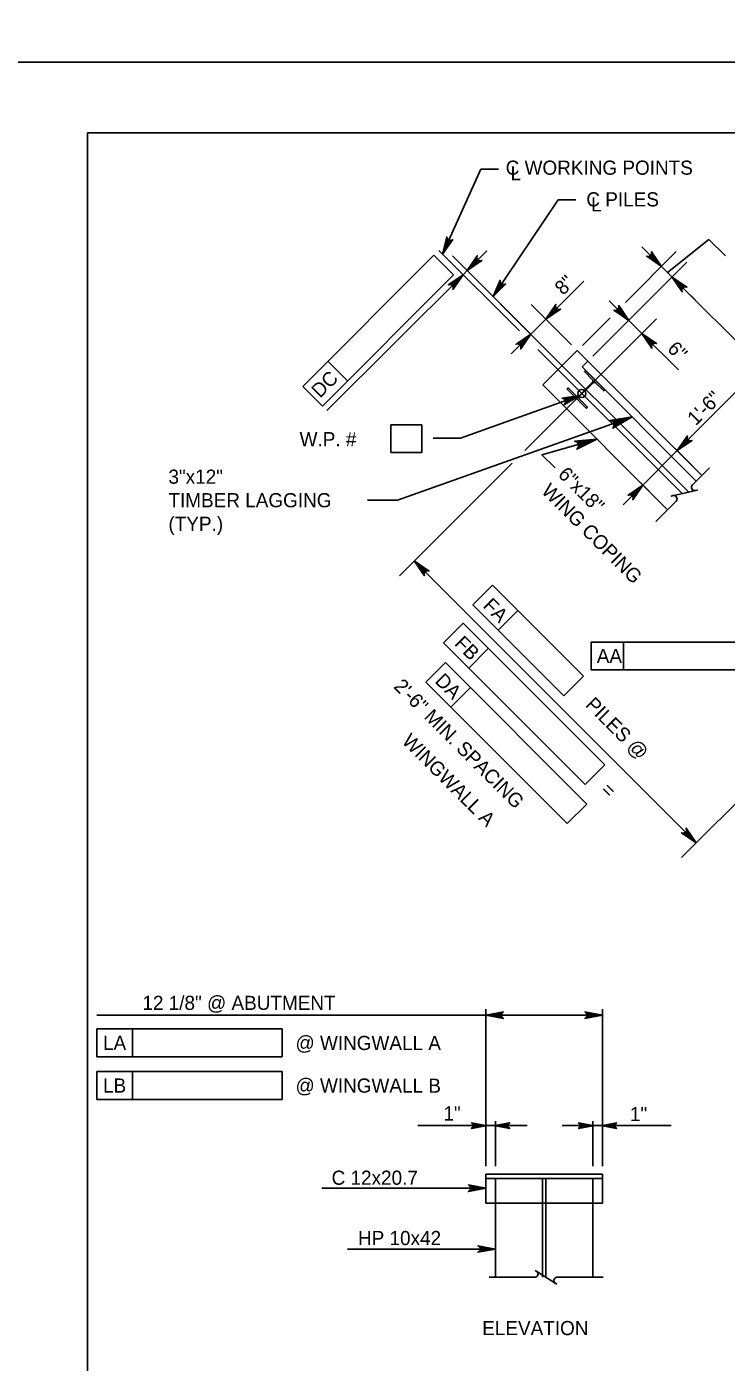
# Model space of a CAD drawing. Extents: x 638304 to 640306, y 296653 to 298435.
# Drawn here: x 639303.6 to 639451.8, y 297565.8 to 297849 of the extents above; entities that cross this region are included whole.
import ezdxf

# ---------------------------------------------------------------- set-up
doc = ezdxf.new("R2010")
doc.units = 0
for name, color, linetype in [('1', 7, 'Continuous'), ('2', 7, 'Continuous'), ('3', 7, 'Continuous'), ('4', 7, 'Continuous'), ('Level 2', 7, 'Continuous'), ('Level 3', 7, 'Continuous'), ('Level 4', 7, 'Continuous'), ('Level 5', 7, 'Continuous'), ('Level 52', 7, 'Continuous'), ('Level 8', 7, 'Continuous'), ('PLT-BNDY', 7, 'Continuous')]:
    doc.layers.add(name, color=color, linetype=linetype)

# ---------------------------------------------------------------- blocks, each defined once
blk = doc.blocks.new('HPILE')
at = {"layer": '3'}
for p, q in [((-0.12, -2.66), (-0.12, 2.66)), ((0.12, 2.66), (0.12, -2.66)), ((-3.67, -3.1), (-0.56, -3.1))]:
    blk.add_line(p, q, dxfattribs=at)
for points in [[(-0.56, 3.1), (-3.67, 3.1), (-3.67, 3.54), (3.67, 3.54), (3.67, 3.1), (0.56, 3.1)], [(0.56, -3.1), (3.67, -3.1), (3.67, -3.54), (-3.67, -3.54), (-3.67, -3.1)]]:
    blk.add_lwpolyline(points, dxfattribs=at)
for centre, start, end in [((-0.56, 2.66), 0, 90), ((0.56, 2.66), 90, 180), ((-0.56, -2.66), 270, 0), ((0.56, -2.66), 180, 270)]:
    blk.add_arc(centre, 0.438, start, end, dxfattribs=at)
blk = doc.blocks.new('LT')
at = {"layer": '1'}
blk.add_lwpolyline([(0, 0), (-11.2, -2.1), (-10.8, -1.8), (-10.3, -1.5), (-10.1, -1.1), (-9.9, -0.8), (-9.8, -0.4), (-9.8, 0), (-9.8, 0.4), (-9.9, 0.8), (-10.1, 1.1), (-10.3, 1.5), (-10.8, 1.8), (-11.2, 2.1), (0, 0), (-10.8, 1.8), (-10.3, 1.5), (0, 0), (-10.1, 1.1), (-9.9, 0.8), (0, 0), (-9.8, 0.4), (-9.8, 0), (0, 0), (-9.8, -0.4), (-9.9, -0.8), (0, 0), (-10.1, -1.1), (-10.3, -1.5), (0, 0), (-10.8, -1.8)], dxfattribs=at)

msp = doc.modelspace()

# ---------------------------------------------------------------- linework, layer by layer
at = {"layer": '2'}
for p, q in [((639316.46, 297262.46), (639316.46, 297826.46)), ((639316.46, 297826.46), (640102.46, 297826.46))]:
    msp.add_line(p, q, dxfattribs=at)
at = {"layer": '4'}
for p, q in [((639409.63, 297615.95), (639386.5, 297615.95)), ((639440.19, 297615.95), (639417.06, 297615.95))]:
    msp.add_line(p, q, dxfattribs=at)
at = {"layer": 'Level 2'}
for p, q in [((639420.25, 297780.28), (639412.95, 297772.99)), ((639446.69, 297753.83), (639420.25, 297780.28)), ((639439.4, 297746.54), (639412.95, 297772.99))]:
    msp.add_line(p, q, dxfattribs=at)
at = {"layer": 'Level 3'}
for p, q in [((639422.51, 297778.02), (639421.29, 297776.81)), ((639445.48, 297752.62), (639421.29, 297776.81)), ((639400.89, 297605.62), (639400.89, 297599.48)), ((639400.89, 297605.62), (639425.58, 297605.62)), ((639400.89, 297604.76), (639425.58, 297604.76)), ((639402.94, 297604.76), (639402.94, 297599.48)), ((639412.89, 297604.76), (639412.89, 297583.79)), ((639413.58, 297604.76), (639413.58, 297583.79)), ((639423.54, 297604.76), (639423.54, 297599.48)), ((639425.58, 297599.48), (639425.58, 297605.62)), ((639400.89, 297599.48), (639425.58, 297599.48)), ((639402.94, 297599.48), (639402.94, 297583.79)), ((639423.54, 297583.79), (639423.54, 297599.48)), ((639411.32, 297585.24), (639415.93, 297582.34)), ((639401.61, 297583.79), (639411.26, 297583.79)), ((639415.92, 297583.79), (639425.78, 297583.79))]:
    msp.add_line(p, q, dxfattribs=at)
for centre, start, end in [((639411.26, 297584.47), 270, 60), ((639415.98, 297583.12), 95.3286, 237.8672)]:
    msp.add_arc(centre, 0.681, start, end, dxfattribs=at)
at = {"layer": 'Level 4'}
for p, q in [((639399.8, 297818.72), (639403.57, 297818.72)), ((639416.22, 297812.24), (639419.97, 297812.24)), ((639439.41, 297796.82), (639448.16, 297803.87)), ((639448.16, 297803.87), (639451.65, 297800.38)), ((639362.06, 297772.69), (639389.85, 297800.48)), ((639389.85, 297800.48), (639394.02, 297796.31)), ((639407.98, 297784.45), (639390.9, 297801.52)), ((639410.2, 297783.97), (639393.79, 297800.38)), ((639396.92, 297797.25), (639401.08, 297801.42)), ((639430.45, 297790.49), (639441.22, 297801.26)), ((639440.35, 297795.87), (639433.93, 297802.3)), ((639438.1, 297798.13), (639435.49, 297800.73)), ((639396.91, 297797.25), (639396.05, 297796.38)), ((639423.59, 297779.11), (639443.48, 297799)), ((639366.23, 297768.52), (639394.02, 297796.31)), ((639396.05, 297796.38), (639367.21, 297767.55)), ((639413.58, 297786.95), (639421.64, 297795)), ((639499.58, 297736.64), (639440.35, 297795.87)), ((639443.13, 297793.09), (639445.22, 297791.01)), ((639443.88, 297750.29), (639403.95, 297790.21)), ((639419.05, 297781.48), (639410.46, 297790.07)), ((639423.59, 297779.11), (639434.29, 297789.81)), ((639431.17, 297786.69), (639427, 297790.85)), ((639437.07, 297787.03), (639409.13, 297759.09)), ((639410.4, 297783.76), (639413.58, 297786.95)), ((639421.33, 297781.37), (639427.23, 297787.26)), ((639431.17, 297786.69), (639433.95, 297783.91)), ((639410.4, 297783.76), (639406.23, 297779.6)), ((639433.95, 297783.91), (639441.68, 297776.18)), ((639442.46, 297749.97), (639411.91, 297780.51)), ((639367.4, 297778.03), (639371.57, 297773.86)), ((639441.46, 297759.07), (639457.07, 297774.69)), ((639362.06, 297772.69), (639366.23, 297768.52)), ((639380.76, 297764.56), (639387.33, 297764.56)), ((639380.76, 297758.66), (639380.76, 297764.56)), ((639387.33, 297758.66), (639387.33, 297764.56)), ((639387.33, 297758.66), (639380.76, 297758.66)), ((639434.16, 297751.78), (639441.46, 297759.07)), ((639441.02, 297759.51), (639444.58, 297755.95)), ((639406.46, 297756.42), (639382.59, 297732.55)), ((639434.16, 297751.78), (639429.99, 297747.61)), ((639433.72, 297752.22), (639437.29, 297748.65)), ((639445.48, 297675.91), (639385.71, 297735.67)), ((639402.29, 297730.52), (639398.13, 297726.35)), ((639402.29, 297730.52), (639421.55, 297711.26)), ((639398.13, 297726.35), (639417.39, 297707.09)), ((639407.63, 297725.18), (639403.46, 297721.02)), ((639396.07, 297722.47), (639391.9, 297718.31)), ((639396.07, 297722.47), (639426.08, 297692.46)), ((639391.9, 297718.31), (639421.91, 297688.3)), ((639423.21, 297718.45), (639458.44, 297718.45)), ((639423.21, 297712.56), (639423.21, 297718.45)), ((639430.04, 297712.56), (639430.04, 297718.45)), ((639401.4, 297717.14), (639397.24, 297712.97)), ((639392.3, 297714.15), (639388.13, 297709.98)), ((639392.3, 297714.15), (639422.31, 297684.14)), ((639458.44, 297712.56), (639423.21, 297712.56)), ((639388.13, 297709.98), (639418.14, 297679.98)), ((639421.55, 297711.26), (639417.39, 297707.09)), ((639479.91, 297710.34), (639442.35, 297672.78)), ((639397.64, 297708.82), (639393.47, 297704.65)), ((639426.08, 297692.46), (639421.91, 297688.3)), ((639422.31, 297684.14), (639418.14, 297679.98)), ((639400.89, 297639.35), (639318.43, 297639.35)), ((639400.89, 297607.38), (639400.89, 297640.65)), ((639425.58, 297639.35), (639400.89, 297639.35)), ((639425.58, 297607.38), (639425.58, 297640.65)), ((639318.43, 297636.44), (639357.73, 297636.44)), ((639318.43, 297636.44), (639318.43, 297630.54)), ((639325.98, 297636.44), (639325.98, 297630.54)), ((639357.73, 297636.44), (639357.73, 297630.54)), ((639318.43, 297630.54), (639357.73, 297630.54)), ((639318.43, 297627.39), (639357.73, 297627.39)), ((639318.43, 297627.39), (639318.43, 297621.5)), ((639325.98, 297627.39), (639325.98, 297621.5)), ((639357.73, 297627.39), (639357.73, 297621.5)), ((639318.43, 297621.5), (639357.73, 297621.5)), ((639402.94, 297607.38), (639402.94, 297616.91)), ((639423.54, 297607.38), (639423.54, 297616.91))]:
    msp.add_line(p, q, dxfattribs=at)
for points in [[(639391.71, 297800.71), (639399.8, 297818.72)], [(639402.43, 297791.73), (639416.22, 297812.24)], [(639391.71, 297800.71), (639392.6, 297804.39), (639392.67, 297804.05), (639392.83, 297803.81), (639393.04, 297803.67), (639393.29, 297803.61), (639393.58, 297803.64), (639393.87, 297803.82), (639391.71, 297800.71), (639393.58, 297803.64), (639393.29, 297803.61), (639391.71, 297800.71), (639393.04, 297803.67), (639392.83, 297803.81), (639391.71, 297800.71), (639392.67, 297804.05)], [(639396.92, 297797.25), (639399.05, 297800.38), (639398.99, 297800.03), (639399.06, 297799.75), (639399.21, 297799.54), (639399.42, 297799.4), (639399.7, 297799.33), (639400.04, 297799.39), (639396.92, 297797.25), (639399.7, 297799.33), (639399.42, 297799.4), (639396.92, 297797.25), (639399.21, 297799.54), (639399.06, 297799.75), (639396.92, 297797.25), (639398.99, 297800.03)], [(639438.1, 297798.13), (639434.97, 297800.27), (639435.31, 297800.21), (639435.59, 297800.28), (639435.8, 297800.42), (639435.95, 297800.63), (639436.02, 297800.91), (639435.96, 297801.25), (639438.1, 297798.13), (639436.02, 297800.91), (639435.95, 297800.63), (639438.1, 297798.13), (639435.8, 297800.42), (639435.59, 297800.28), (639438.1, 297798.13), (639435.31, 297800.21)], [(639396.05, 297796.38), (639393.91, 297793.25), (639393.97, 297793.6), (639393.9, 297793.88), (639393.75, 297794.09), (639393.54, 297794.23), (639393.26, 297794.3), (639392.92, 297794.24), (639396.05, 297796.38), (639393.26, 297794.3), (639393.54, 297794.23), (639396.05, 297796.38), (639393.75, 297794.09), (639393.9, 297793.88), (639396.05, 297796.38), (639393.97, 297793.6)], [(639402.43, 297791.73), (639403.93, 297795.21), (639403.94, 297794.86), (639404.06, 297794.6), (639404.24, 297794.42), (639404.47, 297794.32), (639404.76, 297794.3), (639405.09, 297794.43), (639402.43, 297791.73), (639404.76, 297794.3), (639404.47, 297794.32), (639402.43, 297791.73), (639404.24, 297794.42), (639404.06, 297794.6), (639402.43, 297791.73), (639403.94, 297794.86)], [(639440.35, 297795.87), (639443.48, 297793.74), (639443.14, 297793.8), (639442.85, 297793.72), (639442.65, 297793.58), (639442.5, 297793.37), (639442.43, 297793.09), (639442.49, 297792.75), (639440.35, 297795.87), (639442.43, 297793.09), (639442.5, 297793.37), (639440.35, 297795.87), (639442.65, 297793.58), (639442.85, 297793.72), (639440.35, 297795.87), (639443.14, 297793.8)], [(639413.58, 297786.95), (639415.72, 297790.07), (639415.66, 297789.73), (639415.73, 297789.45), (639415.88, 297789.24), (639416.08, 297789.09), (639416.36, 297789.02), (639416.71, 297789.08), (639413.58, 297786.95), (639416.36, 297789.02), (639416.08, 297789.09), (639413.58, 297786.95), (639415.88, 297789.24), (639415.73, 297789.45), (639413.58, 297786.95), (639415.66, 297789.73)], [(639431.17, 297786.69), (639428.04, 297788.82), (639428.39, 297788.76), (639428.67, 297788.83), (639428.87, 297788.98), (639429.02, 297789.19), (639429.09, 297789.47), (639429.03, 297789.81), (639431.17, 297786.69), (639429.09, 297789.47), (639429.02, 297789.19), (639431.17, 297786.69), (639428.87, 297788.98), (639428.67, 297788.83), (639431.17, 297786.69), (639428.39, 297788.76)], [(639410.4, 297783.76), (639408.26, 297780.64), (639408.33, 297780.98), (639408.25, 297781.27), (639408.11, 297781.47), (639407.9, 297781.62), (639407.62, 297781.69), (639407.28, 297781.63), (639410.4, 297783.76), (639407.62, 297781.69), (639407.9, 297781.62), (639410.4, 297783.76), (639408.11, 297781.47), (639408.25, 297781.27), (639410.4, 297783.76), (639408.33, 297780.98)], [(639433.95, 297783.91), (639437.07, 297781.77), (639436.73, 297781.83), (639436.45, 297781.76), (639436.24, 297781.61), (639436.09, 297781.41), (639436.02, 297781.13), (639436.08, 297780.78), (639433.95, 297783.91), (639436.02, 297781.13), (639436.09, 297781.41), (639433.95, 297783.91), (639436.24, 297781.61), (639436.45, 297781.76), (639433.95, 297783.91), (639436.73, 297781.83)], [(639420.79, 297770.75), (639395.49, 297761.74), (639389.7, 297761.74)], [(639420.79, 297770.75), (639417.52, 297768.84), (639417.72, 297769.13), (639417.77, 297769.41), (639417.73, 297769.66), (639417.61, 297769.88), (639417.38, 297770.07), (639417.05, 297770.16), (639420.79, 297770.75), (639417.38, 297770.07), (639417.61, 297769.88), (639420.79, 297770.75), (639417.73, 297769.66), (639417.77, 297769.41), (639420.79, 297770.75), (639417.72, 297769.13)], [(639431.87, 297766.23), (639382.14, 297748.55), (639375.82, 297748.55)], [(639424.38, 297761.52), (639412.78, 297758.18), (639415.55, 297755.41)], [(639441.46, 297759.07), (639443.59, 297762.2), (639443.53, 297761.85), (639443.6, 297761.57), (639443.75, 297761.37), (639443.96, 297761.22), (639444.24, 297761.15), (639444.58, 297761.21), (639441.46, 297759.07), (639444.24, 297761.15), (639443.96, 297761.22), (639441.46, 297759.07), (639443.75, 297761.37), (639443.6, 297761.57), (639441.46, 297759.07), (639443.53, 297761.85)], [(639434.16, 297751.78), (639432.02, 297748.65), (639432.09, 297749), (639432.01, 297749.28), (639431.87, 297749.48), (639431.66, 297749.63), (639431.38, 297749.7), (639431.04, 297749.64), (639434.16, 297751.78), (639431.38, 297749.7), (639431.66, 297749.63), (639434.16, 297751.78), (639431.87, 297749.48), (639432.01, 297749.28), (639434.16, 297751.78), (639432.09, 297749)], [(639385.71, 297735.67), (639388.84, 297733.54), (639388.49, 297733.6), (639388.21, 297733.53), (639388.01, 297733.38), (639387.86, 297733.17), (639387.79, 297732.89), (639387.85, 297732.55), (639385.71, 297735.67), (639387.79, 297732.89), (639387.86, 297733.17), (639385.71, 297735.67), (639388.01, 297733.38), (639388.21, 297733.53), (639385.71, 297735.67), (639388.49, 297733.6)], [(639445.48, 297675.91), (639442.35, 297678.04), (639442.7, 297677.98), (639442.98, 297678.05), (639443.19, 297678.2), (639443.33, 297678.41), (639443.4, 297678.69), (639443.34, 297679.03), (639445.48, 297675.91), (639443.4, 297678.69), (639443.33, 297678.41), (639445.48, 297675.91), (639443.19, 297678.2), (639442.98, 297678.05), (639445.48, 297675.91), (639442.7, 297677.98)], [(639400.89, 297639.35), (639404.61, 297640.05), (639404.47, 297639.95), (639404.32, 297639.85), (639404.25, 297639.73), (639404.18, 297639.6), (639404.16, 297639.48), (639404.13, 297639.35), (639404.16, 297639.23), (639404.18, 297639.1), (639404.25, 297638.98), (639404.32, 297638.85), (639404.47, 297638.75), (639404.61, 297638.65), (639400.89, 297639.35), (639404.47, 297638.75), (639404.32, 297638.85), (639400.89, 297639.35), (639404.25, 297638.98), (639404.18, 297639.1), (639400.89, 297639.35), (639404.16, 297639.23), (639404.13, 297639.35), (639400.89, 297639.35), (639404.16, 297639.48), (639404.18, 297639.6), (639400.89, 297639.35), (639404.25, 297639.73), (639404.32, 297639.85), (639400.89, 297639.35), (639404.47, 297639.95)], [(639425.58, 297639.35), (639421.86, 297638.65), (639422.01, 297638.75), (639422.15, 297638.85), (639422.22, 297638.98), (639422.3, 297639.1), (639422.32, 297639.23), (639422.34, 297639.35), (639422.32, 297639.48), (639422.3, 297639.6), (639422.22, 297639.73), (639422.15, 297639.85), (639422.01, 297639.95), (639421.86, 297640.05), (639425.58, 297639.35), (639422.01, 297639.95), (639422.15, 297639.85), (639425.58, 297639.35), (639422.22, 297639.73), (639422.3, 297639.6), (639425.58, 297639.35), (639422.32, 297639.48), (639422.34, 297639.35), (639425.58, 297639.35), (639422.32, 297639.23), (639422.3, 297639.1), (639425.58, 297639.35), (639422.22, 297638.98), (639422.15, 297638.85), (639425.58, 297639.35), (639422.01, 297638.75)], [(639400.89, 297602.68), (639366.12, 297602.68)], [(639400.89, 297602.68), (639397.17, 297601.98), (639397.31, 297602.08), (639397.46, 297602.18), (639397.53, 297602.31), (639397.6, 297602.43), (639397.62, 297602.56), (639397.65, 297602.68), (639397.62, 297602.81), (639397.6, 297602.93), (639397.53, 297603.06), (639397.46, 297603.18), (639397.31, 297603.28), (639397.17, 297603.38), (639400.89, 297602.68), (639397.31, 297603.28), (639397.46, 297603.18), (639400.89, 297602.68), (639397.53, 297603.06), (639397.6, 297602.93), (639400.89, 297602.68), (639397.62, 297602.81), (639397.65, 297602.68), (639400.89, 297602.68), (639397.62, 297602.56), (639397.6, 297602.43), (639400.89, 297602.68), (639397.53, 297602.31), (639397.46, 297602.18), (639400.89, 297602.68), (639397.31, 297602.08)], [(639402.94, 297589.78), (639399.21, 297589.08), (639399.36, 297589.18), (639399.5, 297589.28), (639399.58, 297589.41), (639399.65, 297589.53), (639399.67, 297589.66), (639399.69, 297589.78), (639399.67, 297589.9), (639399.65, 297590.03), (639399.58, 297590.15), (639399.5, 297590.28), (639399.36, 297590.38), (639399.21, 297590.48), (639402.94, 297589.78), (639399.36, 297590.38), (639399.5, 297590.28), (639402.94, 297589.78), (639399.58, 297590.15), (639399.65, 297590.03), (639402.94, 297589.78), (639399.67, 297589.9), (639399.69, 297589.78), (639402.94, 297589.78), (639399.67, 297589.66), (639399.65, 297589.53), (639402.94, 297589.78), (639399.58, 297589.41), (639399.5, 297589.28), (639402.94, 297589.78), (639399.36, 297589.18)], [(639402.94, 297589.78), (639371.54, 297589.78)]]:
    msp.add_lwpolyline(points, dxfattribs=at)
for points in [[(639391.71, 297800.71), (639393.14, 297803.3), (639392.7, 297803.5)], [(639436.36, 297800.56), (639435.67, 297799.87), (639438.1, 297798.13)], [(639398.65, 297799.68), (639399.35, 297798.99), (639396.91, 297797.25)], [(639393.61, 297794.64), (639394.31, 297793.95), (639396.05, 297796.38)], [(639402.43, 297791.73), (639404.28, 297794.04), (639403.87, 297794.32)], [(639442.79, 297794.14), (639442.09, 297793.44), (639440.35, 297795.87)], [(639415.32, 297789.38), (639416.01, 297788.68), (639413.58, 297786.95)], [(639429.43, 297789.12), (639428.74, 297788.42), (639431.17, 297786.69)], [(639407.97, 297782.03), (639408.66, 297781.33), (639410.4, 297783.76)], [(639436.38, 297782.17), (639435.68, 297781.48), (639433.95, 297783.91)], [(639420.79, 297770.75), (639417.93, 297769.99), (639418.09, 297769.53)], [(639431.87, 297766.23), (639429.01, 297765.47), (639429.17, 297765.01)], [(639443.19, 297761.5), (639443.89, 297760.81), (639441.46, 297759.07)], [(639431.73, 297750.04), (639432.43, 297749.35), (639434.16, 297751.78)], [(639388.14, 297733.94), (639387.45, 297733.24), (639385.71, 297735.67)], [(639443.74, 297678.34), (639443.05, 297677.64), (639445.48, 297675.91)]]:
    msp.add_lwpolyline(points, close=True, dxfattribs=at)
msp.add_circle((639421.23, 297771.19), 0.849, dxfattribs=at)
at = {"layer": 'Level 52'}
for points in [[(639431.87, 297766.23), (639427.78, 297763.85), (639428.03, 297764.2), (639428.1, 297764.56), (639428.05, 297764.87), (639427.89, 297765.15), (639427.61, 297765.38), (639427.19, 297765.49), (639431.87, 297766.23), (639427.61, 297765.38), (639427.89, 297765.15), (639431.87, 297766.23), (639428.05, 297764.87), (639428.1, 297764.56), (639431.87, 297766.23), (639428.03, 297764.2)], [(639424.38, 297761.52), (639420.15, 297759.39), (639420.43, 297759.73), (639420.52, 297760.08), (639420.48, 297760.4), (639420.35, 297760.68), (639420.08, 297760.93), (639419.67, 297761.07), (639424.38, 297761.52), (639420.08, 297760.93), (639420.35, 297760.68), (639424.38, 297761.52), (639420.48, 297760.4), (639420.52, 297760.08), (639424.38, 297761.52), (639420.43, 297759.73)]]:
    msp.add_lwpolyline(points, dxfattribs=at)
at = {"layer": 'Level 8'}
for p, q in [((639448.25, 297755.39), (639444.67, 297751.81)), ((639441.24, 297748.38), (639436.93, 297744.07))]:
    msp.add_line(p, q, dxfattribs=at)
msp.add_lwpolyline([(639445.35, 297750.62), (639445.7, 297750.7), (639440.17, 297749.44), (639440.54, 297749.53)], dxfattribs=at)
for centre, start, end in [((639445.17, 297751.31), 135, 285), ((639440.7, 297748.84), 320.3286, 102.8672)]:
    msp.add_arc(centre, 0.709, start, end, dxfattribs=at)
at = {"layer": 'PLT-BNDY'}
for points in [[(639276.46, 298435.46), (640117.46, 298435.46), (640117.46, 297841.46), (639276.46, 297841.46)], [(639276.46, 297841.46), (640117.46, 297841.46), (640117.46, 297247.46), (639276.46, 297247.46)]]:
    msp.add_lwpolyline(points, close=True, dxfattribs=at)

# ---------------------------------------------------------------- block references
at = {"layer": '4', "xscale": 0.2682316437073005, "yscale": 0.2682366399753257}
for p in [(639400.84, 297615.95), (639400.84, 297615.95), (639423.53, 297615.95), (639423.53, 297615.95)]:
    msp.add_blockref('LT', p, dxfattribs=at)
at = {"layer": '4', "xscale": 0.2682316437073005, "yscale": 0.2682366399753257, "rotation": 180}
for p in [(639402.89, 297615.95), (639402.89, 297615.95), (639425.58, 297615.95), (639425.58, 297615.95)]:
    msp.add_blockref('LT', p, dxfattribs=at)
at = {"layer": 'Level 3', "xscale": 0.7859001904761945, "yscale": 0.7859001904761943, "rotation": -45.00000000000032}
msp.add_blockref('HPILE', (639422.1, 297772.06), dxfattribs=at)
at = {"layer": 'Level 4', "xscale": 0.26770846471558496, "yscale": 0.2677134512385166}
for p in [(639400.89, 297615.92), (639423.54, 297615.92)]:
    msp.add_blockref('LT', p, dxfattribs=at)
at = {"layer": 'Level 4', "xscale": 0.26770846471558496, "yscale": 0.2677134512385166, "rotation": 180}
for p in [(639402.94, 297615.92), (639425.58, 297615.92)]:
    msp.add_blockref('LT', p, dxfattribs=at)

# ---------------------------------------------------------------- texts
at = {"layer": '4'}
for p in [(639391.89, 297617.03), (639431.42, 297616.91)]:
    msp.add_text('1"', height=3, dxfattribs=at).set_placement(p)
at = {"layer": 'Level 4'}
for s, height, p in [('C WORKING POINTS', 3.0001, (639405.08, 297817.57)), ('L', 3, (639406.11, 297816.37)), ('C PILES', 3, (639422.18, 297810.85)), ('L', 3, (639423.17, 297809.78)), ('W.P. # ', 3, (639361.41, 297759.99)), ('AA', 3, (639424.39, 297714.04)), ('12 1/8" @ ABUTMENT', 3.0001, (639328.09, 297640.47)), ('LA', 3, (639319.75, 297631.99)), ('LB', 3, (639319.74, 297622.95)), ('C 12x20.7', 3, (639368.19, 297603.4)), ('HP 10x42', 3, (639373.78, 297590.61)), ('ELEVATION', 3, (639400.11, 297571.52))]:
    msp.add_text(s, height=height, dxfattribs=at).set_placement(p)
for s, height, rotation, p in [('8"', 3, 45, (639417.28, 297791.87)), ('DC', 3, 45, (639365.72, 297770.06)), ('FA', 3, 314.9382, (639400.1, 297726)), ('FB', 3, 314.9382, (639394.06, 297717.98)), ('2\'-6" MIN. SPACING', 3.0001, 315, (639381.18, 297708.89)), ('DA', 3, 314.9382, (639389.91, 297710.04)), ('PILES @', 3, 314.9382, (639421.79, 297704.98)), ('WINGWALL A', 3, 315, (639382.91, 297697.24)), ('=', 3, 314.9382, (639425.03, 297686.87)), ('@ WINGWALL A', 3.0001, 359.9382, (639360.54, 297631.99)), ('@ WINGWALL B', 3.0001, 359.9382, (639360.54, 297622.95))]:
    msp.add_text(s, height=height, rotation=rotation, dxfattribs=at).set_placement(p)
at = {"layer": 'Level 5'}
for s, height, rotation, p in [('6"', 3, 315, (639439.16, 297780.45)), ('1\'-6"', 3, 45, (639445.38, 297764.22)), ('6"x18"', 3, 315, (639416, 297753.82)), ('WING COPING', 3.0001, 315, (639412.47, 297750.29))]:
    msp.add_text(s, height=height, rotation=rotation, dxfattribs=at).set_placement(p)
for s, height, p in [('3"x12"', 3, (639333.61, 297752.05)), ('TIMBER LAGGING', 3.0001, (639333.61, 297747.06)), ('(TYP.)', 3, (639333.61, 297742.06))]:
    msp.add_text(s, height=height, dxfattribs=at).set_placement(p)

doc.saveas('drawing.dxf')
